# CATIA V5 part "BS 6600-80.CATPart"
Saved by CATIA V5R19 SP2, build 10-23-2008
Part number: BS 6600-80
Bounding box of the stored display mesh (mm): x -59.975 to 59.975, y -59.975 to 59.975, z 0 to 235
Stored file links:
  C:\Users\Bora\Desktop\3D Katı model\BS serisi\BS 6600\BS 6600-80.CATPart
  C:\Program Files\Dassault Systemes\B19\intel_a\reffiles\standard\MetricThickPitch.txt
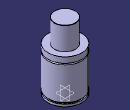
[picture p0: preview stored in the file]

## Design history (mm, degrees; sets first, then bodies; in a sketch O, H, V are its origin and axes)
Body1 (main body)
  Sketch1 on yz-plane, origin (0, 0, 0), H (0, 1, 0), V (0, 0, 1)
    point P1 (60, 134)
    point P2 (60, 129)
    point P3 (60, 134)
    point P7 (37.5, 234)
    point P9 (37.5, 234)
    point P14 (60, 129)
    arc A1 centre (60, 131.5) radius 2.5 from (60, 134) to (60, 129) ccw
    line L1 (60, 134) -> (60, 154)
    line L2 (60, 0) -> (60, 8)
    arc A2 centre (36.5, 234) radius 1 from (37.5, 234) to (36.5, 235) ccw
    line L3 (37.5, 234) -> (37.5, 154)
    line L4 (56, 13) -> (56, 8)
    line L5 (60, 13) -> (60, 129)
    line L6 (36.5, 235) -> (0, 235)
    point P15 (0, 235)
    line L7 (37.5, 154) -> (60, 154)
    line L8 (0, 0) -> (60, 0)
    line L9 (56, 8) -> (60, 8)
    line L10 (56, 13) -> (60, 13)
    coincidence: P15 V, P1 P3, P2 P14, P7 P9
    tangency: L6 A2
    horizontal: L7 H, L8 H, L9 H, L10 H
  Shaft1: profile Sketch1, axis Sketch1.V, angle 360
  Sketch2 on face of Shaft1 from Sketch1.L8, origin (0, 0, 0), H (1, 0, 0), V (0, -1, 0)
    point P1 (40, 0)
    distance P1 V = 40
  Hole1: placed by Sketch2, at (40, 0, 0) direction (0, 0, 1), diameter 8.376, depth 8, threaded "M10", thread diameter 10, thread depth 8, pitch 1.5
  CircPattern1: of Hole1, instances 4, angular step 90, axis from xy-plane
